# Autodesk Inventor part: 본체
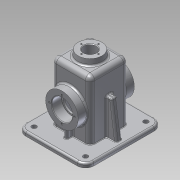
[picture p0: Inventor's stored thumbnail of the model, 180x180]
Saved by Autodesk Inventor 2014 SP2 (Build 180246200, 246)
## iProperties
Created: 2016-08
Part Number: 본체
Material: 알루미늄 6061
Document SubType Name: Modeling
Designer: user
Density: 2.71 g/cm^3
Appearance: 알루미늄 - 평지
Mass: 796.489 g
Surface Area: 912.85 cm^2
Volume: 293.907 cm^3
Author: user
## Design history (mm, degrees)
sketch "스케치1"
  geometry: L1 (-57.5, 65)-(57.5, 65); L2 (57.5, 65)-(57.5, -65); L3 (57.5, -65)-(-57.5, -65); L4 (-57.5, -65)-(-57.5, 65); L5 (-57.5, 65)-(57.5, -65); L6 (57.5, 65)-(-57.5, -65); 1 further point
  constraints: 12 end point, 2 midpoint, 2 parallel, 1 horizontal, 1 perpendicular
  dimensions: "d0" = 115 distance of L2.end L3.end; "d1" = 130 distance of L1.end L2.end
extrude "돌출1" new body sketch "스케치1" distance "d2" = 7; taper "d3" = 0 deg
fillet "모깎기1" dims "d4" = 14
sketch "스케치2"
  geometry: L1 (43.5, 65)-(-43.5, 65) reference; L2 (-57.5, 51)-(-57.5, -51) reference; L3 (-43.5, -65)-(43.5, -65) reference; L4 (57.5, -51)-(57.5, 51) reference; L5 (43.5, -60)-(-43.5, -60); L6 (-52.5, -51)-(-52.5, 51); L7 (-43.5, 60)-(43.5, 60); L8 (52.5, 51)-(52.5, -51); A1 r 14 centre (43.5, 51) between (57.5, 51) and (43.5, 65) reference; A2 r 14 centre (-43.5, 51) between (-43.5, 65) and (-57.5, 51) reference; A3 r 14 centre (-43.5, -51) between (-57.5, -51) and (-43.5, -65) reference; A4 r 14 centre (43.5, -51) between (43.5, -65) and (57.5, -51) reference; A5 r 9 centre (-43.5, -51) between (-52.5, -51) and (-43.5, -60); A6 r 9 centre (-43.5, 51) between (-43.5, 60) and (-52.5, 51); A7 r 9 centre (43.5, 51) between (52.5, 51) and (43.5, 60); A8 r 9 centre (43.5, -51) between (43.5, -60) and (52.5, -51); 1 further point
  constraints: 8 end point, 8 point on circle, 4 centre point, 7 other
  dimensions: "d5" = 5 distance between parallel lines of L5 L3
extrude "돌출2" join sketch "스케치2" distance "d6" = 3; taper "d7" = 0 deg
sketch "스케치3"
  geometry: L1 (-32.5, 32.5)-(32.5, 32.5); L2 (32.5, 32.5)-(32.5, -32.5); L3 (32.5, -32.5)-(-32.5, -32.5); L4 (-32.5, -32.5)-(-32.5, 32.5); L5 (-32.5, 32.5)-(32.5, -32.5); L6 (32.5, 32.5)-(-32.5, -32.5); 1 further point
  constraints: 12 end point, 2 midpoint, 2 parallel, 1 horizontal, 1 perpendicular
  dimensions: "d8" = 65 distance of L2.end L3.end; "d9" = 65 distance of L1.end L2.end
extrude "돌출3" join sketch "스케치3" distance "d10" = 100; taper "d11" = 0 deg
fillet "모깎기2" dims "d12" = 8
fillet "모깎기3" dims "d13" = 8
sketch "스케치4"
  geometry: L1 (-24.5, 107)-(24.5, 107) reference; L2 (-32.5, 7)-(-32.5, 99) reference; L3 (32.5, 99)-(32.5, 7) reference; L4 (27.5, -3)-(27.5, 99); L5 (24.5, 102)-(-24.5, 102); L6 (-27.5, 99)-(-27.5, -3); L7 (-51, -3)-(51, -3) reference; A1 r 8 centre (-24.5, 99) between (-24.5, 107) and (-32.5, 99) reference; A2 r 8 centre (24.5, 99) between (32.5, 99) and (24.5, 107) reference; A3 r 3 centre (24.5, 99) between (27.5, 99) and (24.5, 102); A4 r 3 centre (-24.5, 99) between (-24.5, 102) and (-27.5, 99); 1 further point
  constraints: 6 end point, 4 point on circle, 2 centre point, 2 point on line, 2 other
  dimensions: "d14" = 5 distance between parallel lines of L5 L1; "d15" = 5 distance between parallel lines of L6 L2; "d16" = 5 distance between parallel lines of L3 L4
extrude "돌출4" cut sketch "스케치4" stored distance "d17" = 55; taper "d18" = 0 deg
fillet "모깎기4" dims "d19" = 3
sketch "스케치5"
  geometry: L1 (68, -10)-(-19, -10) reference; C1 r 27.5 at (24.5, 45); 2 further points
  constraints: 1 centre point, 1 midpoint, 1 vertical alignment
  dimensions: "d20" = 55 diameter of C1; "d21" = 55 distance from line of L1 C1.centre
extrude "돌출5" join sketch "스케치5" distance "d22" = 15; taper "d23" = 0 deg
node "작업 평면1"
sketch "스케치14"
  geometry: C1 r 20 at (0, 0); 1 further point
  constraints: 1 centre point, 1 coincident
  dimensions: "d159" = 40 diameter of C1
extrude "돌출10" join sketch "스케치14" stored distance "d160" = 6; taper "d161" = 7 deg
sketch "스케치8"
  geometry: L1 (43.5, 7)-(57.5, 7) reference; L2 (-43.5, 7)-(43.5, 7) reference; L3 (-57.5, 7)-(-43.5, 7) reference; L4 (-49.5, 7)-(-41.068, 67); L5 (-57.5, 7)-(-57.5, 0) reference; L6 (43.5, -3)-(-43.5, -3) reference; L7 (-52.5, -3)-(-43.5, -3) reference; L8 (-32.5, 99)-(-32.5, 7) reference; L9 (-41.068, 67)-(-32.5, 67); 1 further point
  constraints: 4 end point, 2 point on line, 1 perpendicular
  dimensions: "d29" = 8 deg angle of L5 L4; "d30" = 8 distance of L3.start L4.start; "d31" = 70 vertical distance of L4.end L7.start
extrude "돌출7" join sketch "스케치8" stored distance "d32" = 10; taper "d33" = 0 deg
sketch "스케치10"
  geometry: L1 (3, 27.5)-(-3, 27.5); L2 (-3, 27.5)-(-3, 42.5); L3 (-3, 42.5)-(3, 42.5); L4 (3, 42.5)-(3, 27.5); L5 (24.5, 27.5)-(-24.5, 27.5) reference; 2 further points
  constraints: 8 end point, 2 midpoint, 2 parallel, 1 horizontal, 1 perpendicular, 1 vertical alignment
  dimensions: "d37" = 15 distance of L1.end L2.end; "d38" = 6 distance of L2.end L3.end
extrude "돌출9" join sketch "스케치10" stored distance "d39" = 6; taper "d40" = 0 deg
fillet "모깎기18" dims "d162" = 3
hole "구멍11" diameter "d165" = 21; stored, may be unused: countersink angle "d169" = 90 deg, drill point angle "d171" = 0 deg; dims "d163" = 10, "d164" = 10, "d166" = 8, "d167" = 4, "d168" = 2, "d170" = 10
fillet "모깎기6" dims "d51" = 3
fillet "모깎기7" dims "d52" = 3
hole "구멍2" diameter "d55" = 35; stored, may be unused: countersink angle "d59" = 90 deg, drill point angle "d61" = 0 deg; dims "d53" = 10, "d54" = 10, "d56" = 6, "d57" = 4, "d58" = 2, "d60" = 17
hole "구멍3" diameter "d64" = 35; stored, may be unused: countersink angle "d68" = 90 deg, drill point angle "d70" = 0 deg; dims "d62" = 10, "d63" = 10, "d65" = 6, "d66" = 4, "d67" = 2, "d69" = 17
hole "구멍4" diameter "d73" = 30; stored, may be unused: countersink angle "d77" = 90 deg, drill point angle "d79" = 0 deg; dims "d71" = 10, "d72" = 10, "d74" = 6, "d75" = 4, "d76" = 2, "d78" = 17
fillet "모깎기9" dims "d81" = 3
fillet "모깎기10" dims "d82" = 3
fillet "모깎기11" dims "d83" = 3
fillet "모깎기12" dims "d84" = 3
hole "구멍5" diameter "d87" = 8; stored, may be unused: countersink angle "d91" = 90 deg, drill point angle "d93" = 0 deg; dims "d85" = 10, "d86" = 10, "d88" = 6, "d89" = 4, "d90" = 2, "d92" = 17
hole "구멍6" diameter "d96" = 8; stored, may be unused: countersink angle "d100" = 90 deg, drill point angle "d102" = 0 deg; dims "d94" = 10, "d95" = 10, "d97" = 6, "d98" = 4, "d99" = 2, "d101" = 17
hole "구멍7" diameter "d105" = 8; stored, may be unused: countersink angle "d109" = 90 deg, drill point angle "d111" = 0 deg; dims "d103" = 10, "d104" = 10, "d106" = 6, "d107" = 4, "d108" = 2, "d110" = 17
hole "구멍8" diameter "d114" = 8; stored, may be unused: countersink angle "d118" = 90 deg, drill point angle "d120" = 0 deg; dims "d112" = 10, "d113" = 10, "d115" = 6, "d116" = 4, "d117" = 2, "d119" = 17
fillet "모깎기13" dims "d121" = 3
sketch "스케치15"
  geometry: 2 further points
  constraints: 1 vertical alignment
  dimensions: "d172" = 14.5 distance of point (0, 14.5) point (0, 0)
hole "구멍12" sketch "스케치15" at (0, 14.5) diameter "d173" = 2.459; stored, may be unused: countersink angle "d177" = 90 deg, drill point angle "d179" = 118 deg; dims "d174" = 7, "d175" = 4, "d176" = 2, "d178" = 9
sketch "스케치12"
  geometry: C1 r 15 at (0, 0) reference; 2 further points
  constraints: 1 horizontal alignment
  dimensions: "d133" = 21 distance of point (21, 0) C1.centre
hole "구멍10" sketch "스케치12" at (21, 0) diameter "d134" = 3.242; stored, may be unused: countersink angle "d138" = 90 deg, drill point angle "d140" = 118 deg; dims "d135" = 8, "d136" = 4, "d137" = 2, "d139" = 10
fillet "모깎기14" dims "d144" = 0.3
sketch "스케치13"
  geometry: L1 (57, 0)-(57, 92) reference; L2 (44.5, -18)-(4.5, -18) reference; 2 further points
  constraints: 1 other
  dimensions: "d145" = 32.5 distance from line of point (24.5, 8) L1; "d183" = 26 distance from line of point (24.5, 8) L2
feature "엠보싱1" sketch "스케치13" dims "d147" = 0.5, "d148" = 0
fillet "모깎기15" dims "d149" = 3
fillet "모깎기16" dims "d150" = 3
chamfer "모따기3" distance "d184" = 1; stored, may be unused: second distance "d185" = 2, angle "d186" = 45 deg
fillet "모깎기17" dims "d151" = 1
chamfer "모따기2" distance "d155" = 1; stored, may be unused: second distance "d156" = 2, angle "d157" = 45 deg
node "솔리드1"
mirror "대칭1"
mirror "대칭2"
mirror "대칭4"
pattern_circular "원형 패턴3" dims angle "d181" = 360 deg
pattern_circular "원형 패턴2" dims angle "d142" = 360 deg
mirror "대칭5"
node "투영된 루프1"
